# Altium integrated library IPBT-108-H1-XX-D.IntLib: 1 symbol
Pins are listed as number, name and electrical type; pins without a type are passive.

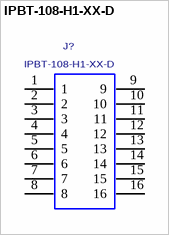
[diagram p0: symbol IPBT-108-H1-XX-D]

## IPBT-108-H1-XX-D
designator J?
0.165" DOUBLE ROW TERMINAL ASSEMBLY; MANUFACTURER: SAMTEC
footprint IPBT-108-H1-XX-D
pins: 1, 2, 3, 4, 5, 6, 7, 8, 9, 10, 11, 12, 13, 14, 15, 16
